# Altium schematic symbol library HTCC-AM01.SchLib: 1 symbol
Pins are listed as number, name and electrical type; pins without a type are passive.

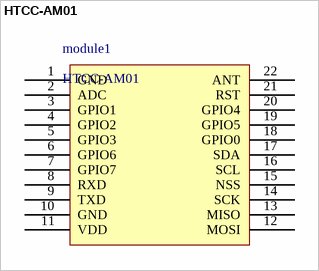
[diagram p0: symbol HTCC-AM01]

## HTCC-AM01
designator module1
footprint PCBComponent_1
pins: 1 GND, 2 ADC, 3 GPIO1, 4 GPIO2, 5 GPIO3, 6 GPIO6, 7 GPIO7, 8 RXD, 9 TXD, 10 GND, 11 VDD, 12 MOSI, 13 MISO, 14 SCK, 15 NSS, 16 SCL, 17 SDA, 18 GPIO0, 19 GPIO5, 20 GPIO4, 21 RST, 22 ANT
